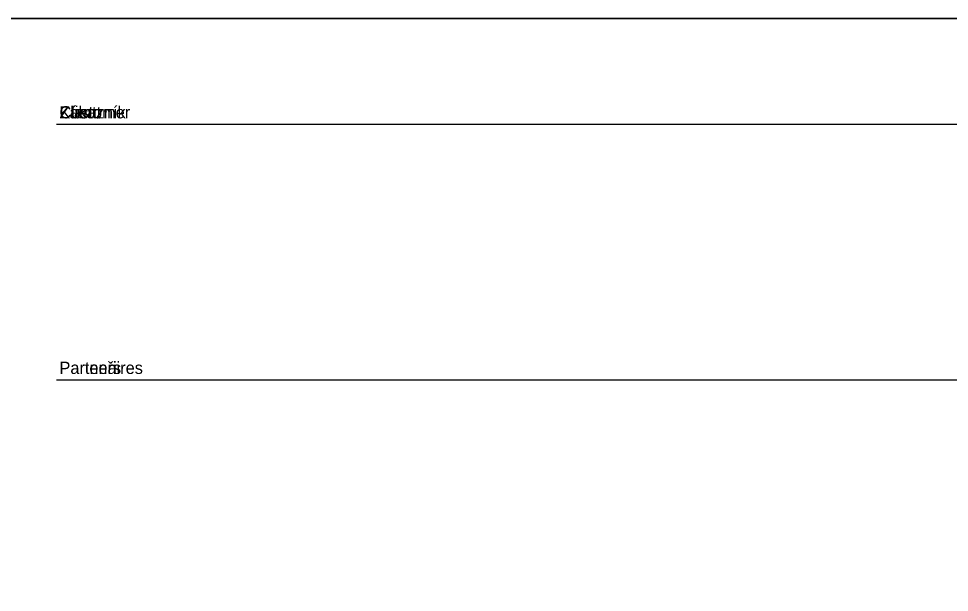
# Model space of a CAD drawing. Extents: x -760612 to 3170, y -975740 to 2995.
# Drawn here: x 680 to 1825, y 2289 to 2995 of the extents above; entities that cross this region are included whole.
import ezdxf

# ---------------------------------------------------------------- set-up
doc = ezdxf.new("R2010")
doc.units = 0
for name, color, linetype in [('Border', 7, 'Continuous'), ('Border_TextCZ', 7, 'Continuous'), ('Border_TextFR', 7, 'Continuous'), ('Border_TextNL', 7, 'Continuous'), ('Border_TextUK', 7, 'Continuous'), ('Implicitní', 7, 'Continuous'), ('Výřez', 7, 'Continuous')]:
    doc.layers.add(name, color=color, linetype=linetype)

# ---------------------------------------------------------------- blocks, each defined once
blk = doc.blocks.new('A3coversheet_v03_CZ_1_1')
at = {"layer": 'Border'}
blk.add_lwpolyline([(0, 0), (4.2, 0), (4.2, 2.97), (0, 2.97)], close=True, dxfattribs=at)
for points in [[(2.1, 0), (2.1, 2.97), (4.2, 2.97)], [(2.1958, 2.8402), (4.1042, 2.8402)], [(2.1958, 2.5258), (4.1042, 2.5258)]]:
    blk.add_lwpolyline(points, dxfattribs=at)
at = {"layer": 'Border_TextCZ'}
for s, p in [('Zákazník', (2.1994, 2.8473)), ('Partneři', (2.1994, 2.533))]:
    blk.add_text(s, height=0.015, dxfattribs=at).set_placement(p)
at = {"layer": 'Border_TextFR'}
for s, p in [('Client', (2.1994, 2.8473)), ('Partenaires', (2.1994, 2.533))]:
    blk.add_text(s, height=0.015, dxfattribs=at).set_placement(p)
at = {"layer": 'Border_TextNL'}
for s, p in [('Klant', (2.1994, 2.8473)), ('Partners', (2.1994, 2.533))]:
    blk.add_text(s, height=0.015, dxfattribs=at).set_placement(p)
at = {"layer": 'Border_TextUK'}
for s, p in [('Customer', (2.1994, 2.8473)), ('Partners', (2.1994, 2.533))]:
    blk.add_text(s, height=0.015, dxfattribs=at).set_placement(p)

msp = doc.modelspace()

# ---------------------------------------------------------------- linework, layer by layer
at = {"layer": 'Implicitní'}
for p, q in [((-150, 2995), (850, 2995)), ((850, 2995), (2731, 2995))]:
    msp.add_line(p, q, dxfattribs=at)
at = {"layer": 'Výřez'}
msp.add_lwpolyline([(-1469, 25), (2731, 25), (2731, 2995), (-1469, 2995)], close=True, dxfattribs=at)

# ---------------------------------------------------------------- block references
at = {"layer": 'Border', "xscale": 1000.0000004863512, "yscale": 1000.0000004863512, "rotation": 4.518606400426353e-10}
msp.add_blockref('A3coversheet_v03_CZ_1_1', (-1469, 25), dxfattribs=at)

doc.saveas('drawing.dxf')
